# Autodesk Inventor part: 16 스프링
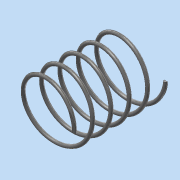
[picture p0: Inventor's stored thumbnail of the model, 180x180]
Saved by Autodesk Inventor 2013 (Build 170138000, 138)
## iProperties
Created: 2016-06
Part Number: 16 스프링
Material: 강철, 탄소
Document SubType Name: Modeling
Designer: Administrator
Density: 7.87 g/cm^3
Mass: 1.63843 g
Surface Area: 8.38135 cm^2
Volume: 0.208187 cm^3
Author: Administrator
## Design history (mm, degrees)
sketch "스케치1"
  geometry: L1 (0, 0)-(8.5, 0); L2 (8.5, 0)-(8.5, 26); L3 (8.5, 26)-(0, 26); L4 (0, 26)-(0, 0); C1 r 0.5 at (8.5, 0)
  constraints: 8 end point, 2 parallel, 1 centre point, 1 coincident, 1 horizontal, 1 perpendicular
  dimensions: "d0" = 26 distance of L3.end L1.start (derived); "d1" = 1 diameter of C1; "d2" = 17 diameter of L2 L4
feature "코일1" sketch "스케치1" pitch "d3" = 10; turns "d5" = 5; dims "d4" = 26 (= d0), "d6" = 0, angle "d7" = 90 deg, angle "d8" = 90 deg, "d9" = 0, "d10" = 0
sketch "스케치2"
  geometry: L1 (0, 15)-(26, 15); L2 (26, 15)-(26, -15); L3 (26, -15)-(0, -15); L4 (0, -15)-(0, 15); 4 further points
  constraints: 8 end point, 2 coincident, 2 midpoint, 2 parallel, 1 horizontal, 1 perpendicular
  dimensions: "d11" = 30 distance of L1.end L2.end
extrude "돌출1" sketch "스케치2" stored distance "d13" = 50; taper "d14" = 0 deg
node "솔리드1"
